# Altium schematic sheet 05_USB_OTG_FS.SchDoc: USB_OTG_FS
size A4; Date: 04/02/2015; Author: P.A.; CompanyName: STMicroelectronics; Organization: Microcontrollers Division; Address1: 12, Rue Jules HOROWITZ; Address2: 38019 Grenoble; Address3: FRANCE; DocumentNumber: 8; Revision: D-01; SheetNumber: 8; SheetTotal: 12; Project: STM32F413H-DISCO
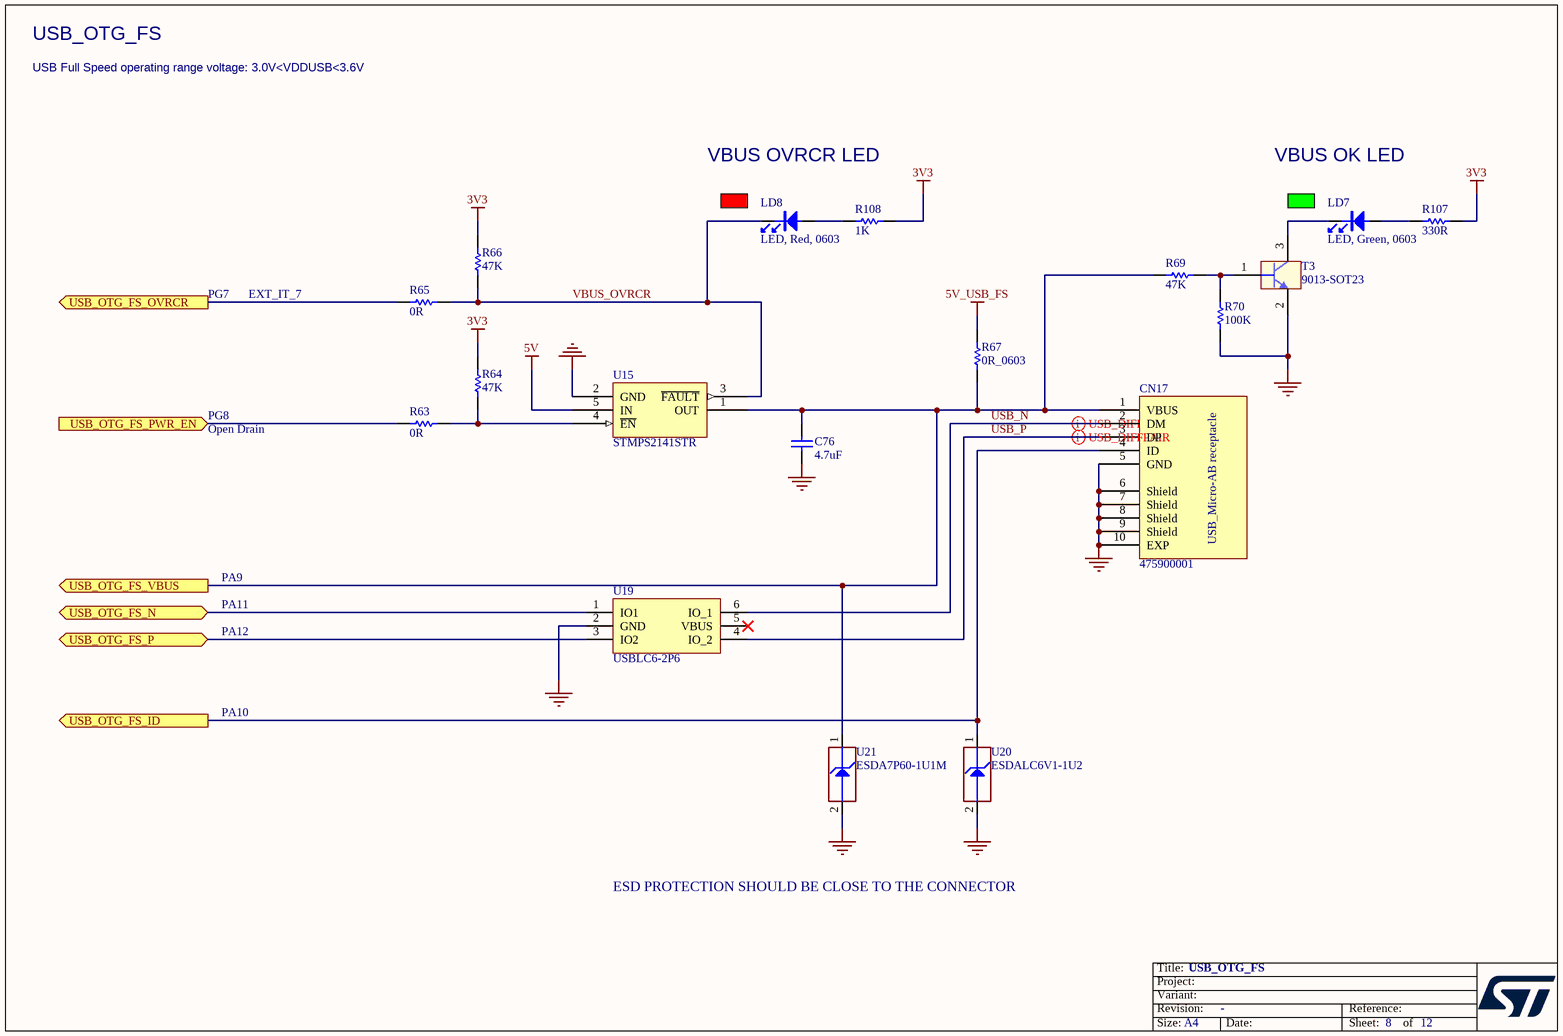
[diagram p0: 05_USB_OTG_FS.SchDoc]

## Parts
C76  4.7uF  [C0603]
CN17  475900001  [CON_USBMICROAB_MOLEX_47590-0001_H3]
LD7  LED, Green, 0603  [LED_0603_GREEN]
LD8  LED, Red, 0603  [LED_0603_RED]
R63  0R  [R0402]
R64  47K  [R0402]
R65  0R  [R0402]
R66  47K  [R0402]
R67  0R_0603  [R0603]
R69  47K  [R0402]
R70  100K  [R0402]
R107  330R  [R0402]
R108  1K  [R0402]
T3  9013-SOT23  [NPN_SOT23]
U15  STMPS2141STR  [MOS_SOT23-5L]
U19  USBLC6-2P6  [ESD_SOT666]
U20  ESDALC6V1-1U2  [ESD_ST0201]
U21  ESDA7P60-1U1M  [ESD_ST0201]

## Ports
USB_OTG_FS_ID (out), USB_OTG_FS_N (bidir), USB_OTG_FS_OVRCR (out), USB_OTG_FS_P (bidir), USB_OTG_FS_PWR_EN (in), USB_OTG_FS_VBUS (out)

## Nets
3V3: R64.2 R66.2 R107.2 R108.1
5V: U15.5(IN)
5V_USB_FS: R67.2
GND: C76.1 CN17.5(GND) CN17.6(Shield) CN17.7(Shield) CN17.8(Shield) CN17.9(Shield) CN17.10(EXP) R70.1 T3.2(E) U15.2(GND) U19.2(GND) U20.2(GND) U21.2(GND)
USB_N: CN17.2(DM) U19.6(IO_1)
USB_OTG_FS_ID: CN17.4(ID) U20.1(IO1) ; port USB_OTG_FS_ID
USB_OTG_FS_N: U19.1(IO1) ; port USB_OTG_FS_N
USB_OTG_FS_OVRCR: R65.1 ; port USB_OTG_FS_OVRCR
USB_OTG_FS_P: U19.3(IO2) ; port USB_OTG_FS_P
USB_OTG_FS_PWR_EN: R63.1 ; port USB_OTG_FS_PWR_EN
USB_OTG_FS_VBUS: C76.2 CN17.1(VBUS) R67.1 R69.1 U15.1(OUT) U21.1(IO1) ; port USB_OTG_FS_VBUS
USB_P: CN17.3(DP) U19.4(IO_2)
VBUS_OVRCR: LD8.2 R65.2 R66.1 U15.3(~{FAULT})
NetLD7_1: LD7.1 R107.1
NetLD7_2: LD7.2 T3.3(C)
NetLD8_1: LD8.1 R108.2
NetR63_2: R63.2 R64.1 U15.4(~{EN})
NetR69_2: R69.2 R70.2 T3.1(B)

Not connected (* = marked no-connect by the designer): U19 5(VBUS)*

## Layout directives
differential pair; rule Matched Net Lengths [Tolerance = 0.5mm]; rule Impedance Constraint [Min = 85.00    Max = 95.00    ]: USB_N, USB_P

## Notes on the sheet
- USB_OTG_FS
- USB Full Speed operating range voltage: 3.0V<VDDUSB<3.6V
- VBUS OVRCR LED
- VBUS OK LED
- PG7
- EXT_IT_7
- Open Drain
- PG8
- PA9
- PA11
- PA12
- PA10
- ESD PROTECTION SHOULD BE CLOSE TO THE CONNECTOR

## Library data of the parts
C76 = Cap_4.7uF_X5R_10%_0603: Capacitor,4.7uF,16V, X5R,10%,0603,YAGEO; Manuf_Part_1: CC0603KRX5R7BB475; Fitted: YES; Order_Code: CC0603KRX5R7BB105; Ordered_By: subcon
CN17 = 475900001: USB-MICRO-AB, 47590-0001, SMT, MOLEX; Fitted: YES; Ordered_By: Subcon
LD7 = LED_green: Manuf_1: everlight; Manuf_Part_1: 19-213SYGC/S530-E2/TR8; ECCN_US/EU: EAR99/NEC; Fitted: YES; Ordered_By: Subcon
LD8 = LED_red: Manuf_1: everlight; Manuf_Part_1: 19-213-R6C-AP1Q2B/3T; ECCN_US/EU: EAR99/NEC; Fitted: YES; Ordered_By: Subcon
R63 R65 = Res_0_5%_0402: Resistor,0R,0402,5%,YAGEO; Manuf_Part_1: RC0402JR-070RL; Fitted: YES; Order_Code: 2363467; Ordered_By: Subcon
R64 R66 R69 = Res_47K_1%_0402: Resistor,47K,0402,1%,YAGEO; Manuf_Part_1: RC0402FR-0747KL; Fitted: YES; Order_Code: 9239430; Ordered_By: Subcon
R67 = Res_0_5%_0603: Resistor,0R,0603,5%,YAGEO; Manuf_Part_1: RC0603JR-070RL; Fitted: YES; Order_Code: 2363481; Ordered_By: subcon
R70 = Res_100K_1%_0402: Resistor,100K,0402,1%,YAGEO; Manuf_Part_1: RC0402FR-07100KL; Manuf_Part_2: RT0402FRE07100KL; Fitted: YES; Ordered_By: Subcon
R107 = Res_330_1%_0402: Resistor,330R,0402,1%,YAGEO; Manuf_Part_1: RC0402FR-07330RL; Fitted: YES; Ordered_By: Subcon
R108 = Res_1K_1%_0402: Resistor,1K,0402,1%,YAGEO; Manuf_Part_1: RC0402FR-071KL; Fitted: YES; Ordered_By: Subcon
T3 = 9013-SOT23: NPN Bipolar Transistor; Manuf_1: NXP; Manuf_Part_1: BSR14; ECCN_US/EU: EAR99/NEC; Fitted: YES; Order_Code: 1081310; Ordered_By: Subcon
U15 = STMPS2141STR: Enhanced single channel power switches; Manuf_1: STM; ECCN_US/EU: EAR99/NEC; Ref St: 9159003; Fitted: YES
U19 = USBLC6-2P6: USB ESD protection; Ordered_By: STM; ECCN_US/EU: EAR99; Fitted: YES
U20 = ESDALC6V1-1U2: Dual Transil array for ESD protection; Manuf_1: STM; Ref St: .; ECCN_US/EU: EAR99/NEC; Fitted: YES; Provided: ST
U21 = MCD-00251: High power transient voltage suppressor, 7V breakdown; Manuf_1: STM; ECCN_US/EU: EAR99/NEC; Fitted: YES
